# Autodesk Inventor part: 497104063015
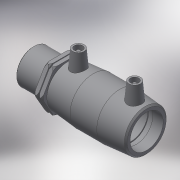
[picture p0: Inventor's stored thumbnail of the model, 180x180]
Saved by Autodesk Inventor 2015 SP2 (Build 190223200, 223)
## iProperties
Created: 2017-06
Part Number: 497104063015
Material: Generic
Description: PLASSON PE MALE TRANSITION COUPLER 63-1.1/2"
Document SubType Name: Modeling
Designer: KIM
Mass: 55.0731 g
Surface Area: 148.067 cm^2
Volume: 55.0731 cm^3
Density: 1 g/cm^3
Appearance: Default
Author: KIM
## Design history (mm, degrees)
derived "497104.ipt"
feature "Solid1::497104.ipt"
tag "TaggingFeature1"
body "Solid1"
other parameters: "d0" = 117, "d1" = 63, "d2" = 82, "d3" = 57, "d4" = 39, "d5" = 73.8, "d6" = 59.85, "d7" = 63, "d8" = 168 deg, "d10" = 22.8, "d11" = 7.6, "d29" = 57, "d30" = 14, "d31" = 40.95, "d34" = 5 deg, "d41" = 4, "d42" = 14, "d43" = 0, "d48" = 3, "d49" = 0, "d57" = 48, "d58" = 47.803, "d59" = 38.2424, "d60" = 39.6, "d61" = 66.9242, "d62" = 0.95606, "d65" = 1.64, "d70" = 0.1, "d71" = 44, "d72" = 11, "d73" = 22.8, "d75" = 0, "d76" = 1.1, "d77" = 4.95, "d78" = 66.9242, "d_" = 63, "L_" = 161, "L_2" = 57, "D_1" = 82, "A_" = 57, "d_2" = 12, "L_1" = 44, "D_" = 48, "R_" = 47.803
